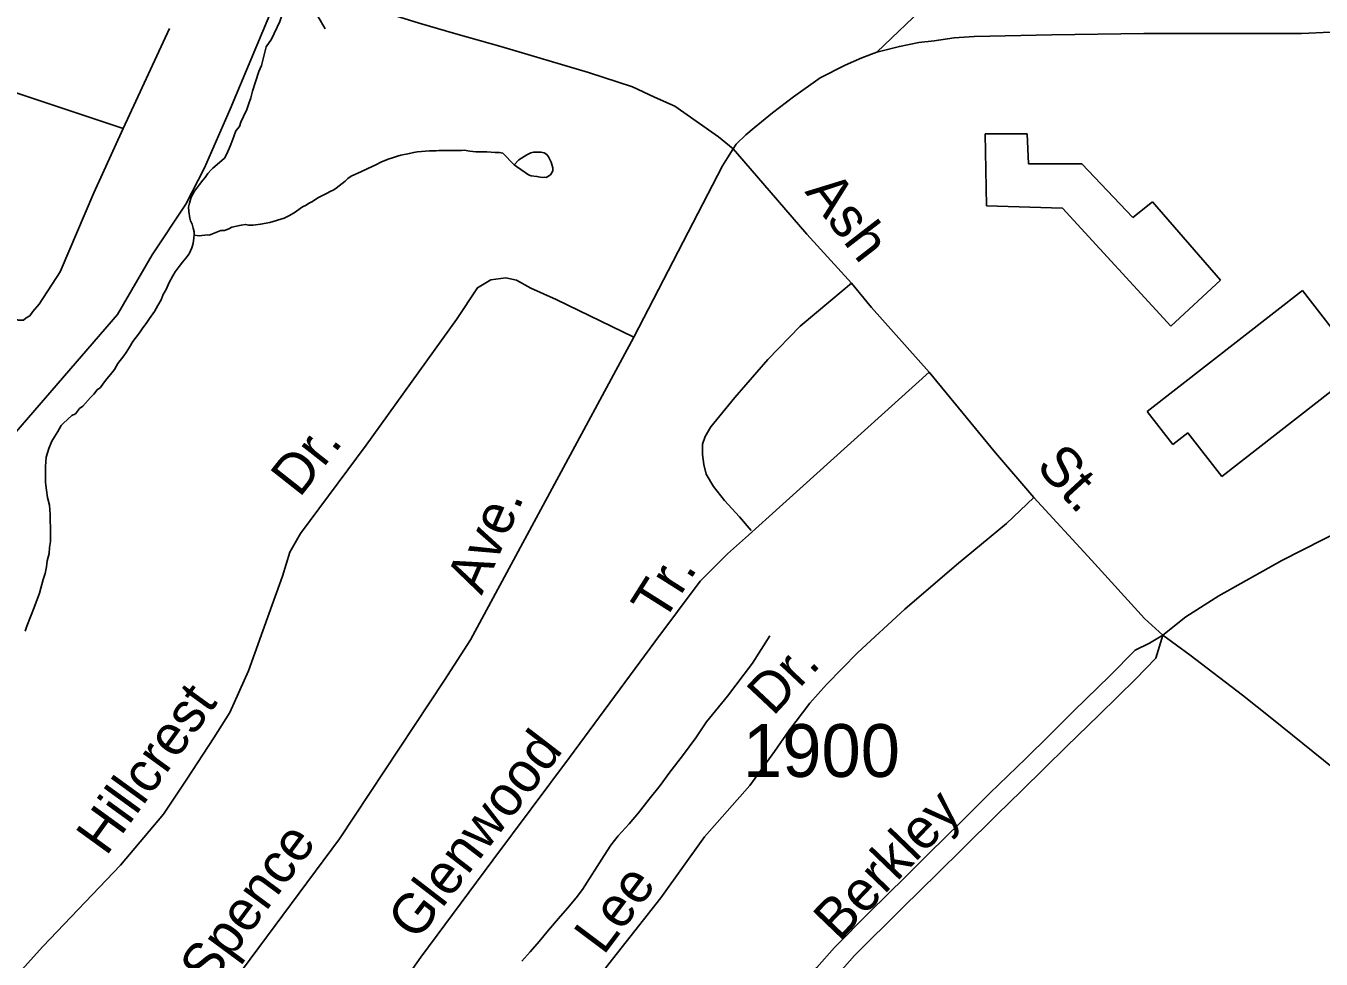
# Model space of a CAD drawing. Extents: x 2260773 to 2342389, y 552869 to 618546.
# Drawn here: x 2309370 to 2312438, y 590931 to 593140 of the extents above; entities that cross this region are included whole.
import ezdxf

# ---------------------------------------------------------------- set-up
doc = ezdxf.new("R2010")
doc.units = 0
for name, color, linetype in [('Exist Cultural Manufacturing Building Footprint', 7, 'Continuous'), ('Exist Hydrographic Creek Single Shore', 7, 'Continuous'), ('Exist Hydrographic Misc Water Feature', 7, 'Continuous'), ('Exist Road Non-System Type 51', 7, 'Continuous'), ('Exist Road Non-System Type 51 Label', 7, 'Continuous'), ('Exist Road Primary US Attributed', 7, 'Continuous'), ('Exist Road Primary US Label', 7, 'Continuous'), ('Exist Road Primary US Structure Standard Bridge CELL', 7, 'Continuous'), ('Exist Road Primary US UnDivided 4 Lane Attributed', 7, 'Continuous'), ('Exist Road Secondary Type 51 Attributed', 7, 'Continuous'), ('Exist Road Secondary Type 51 Label', 7, 'Continuous'), ('Exist Road Secondary Type 51 Number Label', 7, 'Continuous'), ('Exist Road Secondary Type 51 Undivided 4 Lane Attributed', 7, 'Continuous')]:
    doc.layers.add(name, color=color, linetype=linetype)

msp = doc.modelspace()

# ---------------------------------------------------------------- linework, layer by layer
at = {"layer": 'Exist Cultural Manufacturing Building Footprint'}
for p, q in [((2311645.5, 592714.4), (2311642.4, 592884.6)), ((2311642.4, 592884.6), (2311741.4, 592884.6)), ((2311741.4, 592884.6), (2311744.5, 592813.4)), ((2311744.5, 592813.4), (2311871.4, 592813.4)), ((2311871.4, 592813.4), (2311992, 592686.5)), ((2311825, 592708.2), (2311645.5, 592714.4)), ((2311992, 592686.5), (2312038.4, 592723.6)), ((2312038.4, 592723.6), (2312199.3, 592537.9)), ((2312081.7, 592429.5), (2311825, 592708.2)), ((2312202.4, 592073.5), (2312944.9, 592652.4)), ((2312199.3, 592537.9), (2312081.7, 592429.5)), ((2312393.8, 592513.4), (2312026.1, 592226.8)), ((2312461.7, 592426.3), (2312393.8, 592513.4)), ((2312026.1, 592226.8), (2312086.8, 592149)), ((2312086.8, 592149), (2312122.1, 592176.5)), ((2312122.1, 592176.5), (2312202.4, 592073.5))]:
    msp.add_line(p, q, dxfattribs=at)
at = {"layer": 'Exist Hydrographic Creek Single Shore'}
msp.add_lwpolyline([(2308671.2, 590929.8), (2309166.1, 591409.2), (2309239.1, 591510.7), (2309304.1, 591720), (2309316, 592143.8), (2309587.1, 592456.7), (2309669.1, 592597.8), (2309749.3, 592717.8), (2309793.5, 592804.3), (2309853.8, 592943.2), (2309980.5, 593245.1)], dxfattribs=at)
at = {"layer": 'Exist Hydrographic Misc Water Feature'}
for points in [[(2310103.6, 594008.6), (2310055.1, 593882.1), (2310039.7, 593828.1), (2310036.4, 593779.9), (2310032.7, 593760.2), (2310064.9, 593714.4), (2310103.2, 593661.2), (2310121.7, 593633.3), (2310120.1, 593611.2), (2310104.9, 593553), (2310087.7, 593482.7), (2310072.1, 593434.7), (2310054.6, 593360.7), (2310038.2, 593316.5), (2310015.7, 593272.5), (2309998.5, 593228.4), (2309986.2, 593194.6), (2309971.6, 593150.6), (2309951.5, 593108.6), (2309939.4, 593090.5)], [(2309939.4, 593090.5), (2309927.9, 593046), (2309922.2, 593032.3), (2309914.2, 593007.9), (2309906.8, 592985.9), (2309902.9, 592969.9), (2309897.2, 592954.1), (2309893.1, 592941.8), (2309885.3, 592925.9), (2309879.1, 592911.8), (2309875.8, 592901.8), (2309867.6, 592891.6), (2309859.8, 592869.7), (2309854.1, 592855.6), (2309846.3, 592837.3), (2309840.4, 592827.2), (2309834.2, 592821.3), (2309812.5, 592803), (2309808.6, 592799.2), (2309800.8, 592791), (2309794.8, 592781), (2309789.1, 592774.9), (2309781.1, 592764.8), (2309769.6, 592748.7), (2309761.2, 592734.5), (2309757.5, 592720.5), (2309755.5, 592710.6), (2309755.9, 592700.4), (2309758.1, 592684.7), (2309760, 592678.7), (2309764.1, 592670.4), (2309766.3, 592660.8), (2309768.4, 592652.8), (2309768.4, 592644.7)], [(2309768.4, 592644.7), (2309780.5, 592642.8), (2309800.4, 592645.1), (2309804.5, 592644.9), (2309832.2, 592655.3), (2309840.4, 592655.3), (2309850.4, 592659.5), (2309858.2, 592663.6), (2309880.1, 592667.9), (2309890.4, 592670.1), (2309898, 592668.1), (2309908.2, 592668.2), (2309926.1, 592670.3), (2309948, 592674.7), (2309981.6, 592685.1), (2309994.1, 592690.9), (2310007.9, 592699.4), (2310019.8, 592707.4), (2310025.5, 592711.4), (2310033.9, 592715.3), (2310039.7, 592719.3), (2310047.5, 592723.4), (2310063.3, 592734.1), (2310083.3, 592744), (2310091.1, 592748.1), (2310099.1, 592752.2), (2310105.3, 592756.1), (2310126.6, 592772.4), (2310132.8, 592778.8), (2310140.6, 592784.5), (2310164.8, 592795), (2310190.2, 592807), (2310198.6, 592811), (2310210.7, 592817.3), (2310220.3, 592821.6), (2310230.4, 592825.7), (2310238.4, 592827.8), (2310250.1, 592831.7), (2310258.1, 592833.7), (2310278.4, 592838), (2310288.4, 592840.1), (2310297.6, 592842.3), (2310326.1, 592844.5), (2310333.7, 592844.6), (2310341.9, 592844.6), (2310347.9, 592844.9), (2310352, 592844.7), (2310364.1, 592844.9), (2310376, 592845.1), (2310386.2, 592845.3), (2310393.8, 592845.3), (2310401.8, 592845.3), (2310407.9, 592845.6), (2310421.9, 592843.5), (2310435.6, 592841.8), (2310439.9, 592842), (2310449.8, 592842.1), (2310454.1, 592841.9), (2310458, 592842.1), (2310461.7, 592842), (2310481.8, 592840.2), (2310486.1, 592840.3), (2310492, 592840.2), (2310499.8, 592838.7), (2310526.3, 592810.8)], [(2310526.3, 592810.8), (2310532.4, 592807), (2310552.5, 592793), (2310560.5, 592787.4), (2310566.7, 592785.2), (2310580.4, 592783.6), (2310592.7, 592781.3), (2310598.2, 592781.7), (2310602.5, 592781.4), (2310606.2, 592783.7), (2310612.4, 592787.6), (2310616.5, 592793.9), (2310618.3, 592797.7), (2310618.1, 592803.8), (2310616.1, 592811.8), (2310614, 592817.8), (2310607.9, 592829.7), (2310603.8, 592835.6), (2310597.8, 592839.8), (2310589.8, 592841.3), (2310572, 592841.1), (2310565.8, 592839.3), (2310556.2, 592835), (2310550, 592831.1), (2310544.3, 592827.1), (2310537.9, 592822.8), (2310526.3, 592810.8)], [(2309768.4, 592644.7), (2309768.2, 592638.6), (2309766.7, 592624.6), (2309762.9, 592614.6), (2309756.7, 592600.6), (2309749.1, 592590.4), (2309741.1, 592580.6), (2309733.1, 592570.5), (2309723.3, 592558.1), (2309717.9, 592548), (2309709.7, 592532.2), (2309702, 592515.9), (2309695.6, 592503.9), (2309690.3, 592491.7), (2309682.5, 592478), (2309674.5, 592463.7), (2309662.6, 592447.7), (2309655, 592435.4), (2309646.8, 592425.3), (2309639, 592413.5), (2309631.2, 592403.3), (2309623.2, 592393.2), (2309615.4, 592379.3), (2309607.4, 592367.2), (2309601.9, 592359.1), (2309587.7, 592340.9), (2309579.9, 592326.7), (2309570.3, 592314.8), (2309562.1, 592304.6), (2309554.1, 592294.5), (2309546.5, 592284.3), (2309538.7, 592278.5), (2309530.7, 592268.4), (2309522.9, 592260.2), (2309505.1, 592239.8), (2309497.3, 592234.1), (2309487.3, 592221.8), (2309478.9, 592217.8), (2309459.4, 592199.6), (2309453.6, 592193.6), (2309445.6, 592179.4), (2309437.6, 592167.2), (2309431.9, 592157.1), (2309424.1, 592139.3), (2309418.2, 592119.1), (2309416.7, 592097), (2309416.7, 592077.1), (2309416.7, 592059.2), (2309419.2, 592041), (2309421.4, 592023.3), (2309425.7, 592005.2), (2309427.6, 591983.4), (2309427.8, 591969.2), (2309428.2, 591951.3), (2309428.4, 591937.5), (2309428.4, 591919.2), (2309426.4, 591905.3), (2309424.9, 591891.3), (2309420.6, 591873.4), (2309419.2, 591859.4), (2309415.7, 591843.3), (2309411.2, 591829.3), (2309402, 591797.1), (2309390.1, 591763.2), (2309372.4, 591718.8), (2309368.7, 591706.8)], [(2311132, 591696), (2311090.8, 591631.6), (2311031.7, 591553), (2310982.1, 591492.3), (2310956.7, 591454.3), (2310924.9, 591411.7), (2310895.6, 591373.5), (2310872, 591341.4), (2310846.1, 591309.2), (2310820.9, 591276.9), (2310799.2, 591250.6), (2310773.1, 591222.4), (2310755.5, 591200.4), (2310739.9, 591175.9), (2310688.7, 591095.2), (2310673.1, 591075.3), (2310653.2, 591051.1), (2310631.5, 591026.8), (2310607.7, 590998.8), (2310586.1, 590972.4), (2310564.2, 590948.1), (2310544.9, 590925.9)]]:
    msp.add_lwpolyline(points, dxfattribs=at)
at = {"layer": 'Exist Road Non-System Type 51'}
for p, q in [((2311506.3, 593193.2), (2311385.3, 593078)), ((2309600.9, 592896.8), (2309709.9, 593133.6))]:
    msp.add_line(p, q, dxfattribs=at)
for points in [[(2309600.9, 592896.8), (2309432.3, 592953), (2309263.8, 593009.2), (2309136.9, 593049.3)], [(2308983.6, 592570.5), (2309148, 592515.1), (2309274, 592470.8), (2309321.7, 592453.8), (2309340.4, 592447), (2309352.3, 592443.6), (2309364.2, 592443.6), (2309371, 592448.7), (2309379.5, 592453.8), (2309386.4, 592464), (2309401.7, 592481.1), (2309451.1, 592557.7), (2309531.1, 592745.1), (2309600.9, 592896.8)], [(2311045.5, 592849.1), (2311031.8, 592827.4), (2311020.3, 592809), (2310809.8, 592403.5)], [(2310809.8, 592403.5), (2310625.9, 592492.1), (2310566.3, 592519.4), (2310532.2, 592538.1), (2310506.7, 592543.3), (2310471.7, 592538.7), (2310439.9, 592520.3), (2310389.8, 592445.1), (2310176.1, 592147.7), (2310020.5, 591938.2), (2309994.9, 591893.9), (2309977.5, 591837.6), (2309946.4, 591749.3), (2309897.1, 591613), (2309852.8, 591514.2), (2309815.3, 591454.5), (2309751.5, 591356.6), (2309696.1, 591273.9), (2309594, 591153), (2309410, 590960.5), (2309137.6, 590658.9)], [(2311087.5, 591945.5), (2311059.9, 591977.7), (2311024.6, 592016.1), (2310998.6, 592049.8), (2310981.7, 592079), (2310975.6, 592102), (2310972.5, 592125), (2310972.5, 592149.6), (2310978.6, 592168), (2310992.4, 592191), (2311049.2, 592260.1), (2311127.4, 592350.6), (2311204.1, 592428.9), (2311276.2, 592490.3), (2311325.2, 592531.2)], [(2310809.8, 592403.5), (2310423.2, 591686.3), (2310361.9, 591590.8), (2310112.5, 591215.2), (2309883.4, 590905.9)], [(2311509.2, 592320.2), (2311130.7, 591978.5), (2311081.4, 591934.2), (2311032, 591889.9), (2310967.3, 591825.1), (2310860, 591682), (2310657.4, 591407.7), (2310476, 591164.9), (2310305.7, 590934.9), (2310239.3, 590841.2), (2310207, 590795.2), (2310176.3, 590774.7), (2310138.9, 590764.5), (2310098, 590767.9), (2310045.2, 590793.5), (2309883.4, 590905.9)], [(2311757.4, 592023.4), (2311692.4, 591962.3), (2311574.3, 591864.2), (2311451.7, 591759.4), (2311340.3, 591656.8), (2311266.7, 591581), (2311226.6, 591536.4), (2311176.8, 591470.8), (2311143.3, 591422.4), (2311084.4, 591341.8), (2310977, 591219.8), (2310873.6, 591076), (2310751, 590919.3), (2310601.2, 590723.3), (2310575.6, 590670.5), (2310562, 590634.7), (2310553.5, 590599), (2310550.1, 590530.8), (2310550.1, 590377.5), (2310554.9, 590267.8)]]:
    msp.add_lwpolyline(points, dxfattribs=at)
at = {"layer": 'Exist Road Primary US Attributed'}
msp.add_lwpolyline([(2312063.2, 591697.8), (2312128, 591650.5), (2312251.8, 591555.4), (2312321.2, 591500.2), (2312492.2, 591362.5), (2312762.9, 591163.2), (2312960.4, 591025.2), (2313205.6, 590848)], dxfattribs=at)
at = {"layer": 'Exist Road Primary US Structure Standard Bridge CELL'}
msp.add_line((2310044.4, 593192.9), (2310079.2, 593133.3), dxfattribs=at)
at = {"layer": 'Exist Road Primary US UnDivided 4 Lane Attributed'}
for points in [[(2309913.1, 593265.7), (2310064.5, 593220.5), (2310301.3, 593146.5), (2310388.1, 593121.2), (2310495.2, 593091.5), (2310702.8, 593030), (2310807.1, 592995.9), (2310858.7, 592971.7), (2310907.1, 592949.7), (2310957.6, 592914.6), (2311010.3, 592877.2), (2311045.5, 592849.1)], [(2311045.5, 592849.1), (2311115.9, 592767.5), (2311219.7, 592646.6), (2311325.2, 592531.2), (2311373, 592473), (2311509.2, 592320.2), (2311666.2, 592128.9), (2311757.4, 592023.4), (2311893.6, 591875), (2312019.3, 591737.4), (2312063.2, 591697.8)]]:
    msp.add_lwpolyline(points, dxfattribs=at)
at = {"layer": 'Exist Road Secondary Type 51 Attributed'}
for points in [[(2311045.5, 592849.1), (2311052.7, 592859.8), (2311075.1, 592882.2), (2311094.7, 592899), (2311138.1, 592934), (2311188.5, 592971.9), (2311251.4, 593016.9), (2311310.5, 593047.4), (2311349.9, 593064.2), (2311385.3, 593078), (2311439, 593091.5), (2311484.8, 593100.4), (2311521, 593105), (2311568.7, 593112), (2311616.3, 593114.8), (2311799.7, 593119), (2312018.1, 593121.8), (2312391.3, 593121.8), (2312597.1, 593131.6)], [(2312063.2, 591697.8), (2312031.1, 591678.7), (2311997.7, 591662.3), (2311937.2, 591601.6), (2311852, 591518.1), (2311795.5, 591461.3), (2311738.7, 591405.6), (2311653.5, 591323.8), (2311583.6, 591253.7), (2311510.2, 591182.1), (2311453.5, 591125.5), (2311368, 591042), (2311284.9, 590958.3), (2311243.1, 590910.4), (2311218.8, 590880.7), (2311174.9, 590814.5), (2311136.2, 590743.2), (2311103, 590672.5), (2311076, 590586.8), (2311045.8, 590481.5), (2311001.3, 590345.8)], [(2311050.6, 590350.4), (2311062.2, 590373), (2311079.8, 590428.4), (2311093.2, 590479.2), (2311117, 590560), (2311141.3, 590631.8), (2311155.9, 590672.7), (2311171.2, 590707.3), (2311189.1, 590743.1), (2311230.8, 590812.6), (2311279.2, 590878.3), (2311332.7, 590938.8), (2311446.4, 591052.1), (2311530.9, 591134.9), (2311588.2, 591191.5), (2311670.8, 591273.1), (2311728, 591329), (2311783.8, 591383.3), (2311834.5, 591433.7), (2311912.1, 591509.1), (2311999.3, 591594), (2312046.4, 591643.5), (2312063.2, 591697.8)]]:
    msp.add_lwpolyline(points, dxfattribs=at)
at = {"layer": 'Exist Road Secondary Type 51 Undivided 4 Lane Attributed'}
msp.add_lwpolyline([(2312063.2, 591697.8), (2312117.3, 591740.7), (2312195.8, 591790.8), (2312344.5, 591874.4), (2312541.7, 591974.8), (2312819.1, 592111.9), (2313110.6, 592261.5), (2313253.8, 592329.8), (2313418.1, 592422), (2313693.8, 592564.2), (2314006.3, 592719.6), (2314279.3, 592860.4), (2314505.1, 592974.6), (2314724.6, 593090), (2315196.8, 593324.1), (2315407.4, 593434.4), (2315603.2, 593544.7), (2315843.5, 593663.5), (2316007.5, 593751.4), (2316179.4, 593835.7), (2316404.1, 593956.9)], dxfattribs=at)

# ---------------------------------------------------------------- texts
at = {"layer": 'Exist Road Non-System Type 51 Label'}
for s, rotation, p in [('Dr.', 51.7284, (2310018.2, 592021.1)), ('Ave.', 66.5954, (2310449.8, 591790.6)), ('Tr.', 57.7515, (2310879.3, 591724.5)), ('Dr.', 46.8311, (2311139.7, 591504)), ('Hillcrest', 54.0596, (2309560.3, 591172.4)), ('Glenwood', 52.4661, (2310295.8, 590971.2)), ('Spence', 53.5493, (2309804.5, 590860.4)), ('Lee', 53.1546, (2310738.3, 590937.8))]:
    msp.add_text(s, height=95, rotation=rotation, dxfattribs=at).set_placement(p)
at = {"layer": 'Exist Road Primary US Label'}
for s, rotation, p in [('Ash', 307.6913, (2311213.5, 592747)), ('St.', 312.6203, (2311760, 592095.2))]:
    msp.add_text(s, height=95, rotation=rotation, dxfattribs=at).set_placement(p)
at = {"layer": 'Exist Road Secondary Type 51 Label'}
msp.add_text('Berkley', height=95, rotation=46.1655, dxfattribs=at).set_placement((2311295.8, 590970.3))
at = {"layer": 'Exist Road Secondary Type 51 Number Label'}
msp.add_text('1900', height=125, dxfattribs=at).set_placement((2311068.5, 591361.9))

doc.saveas('drawing.dxf')
